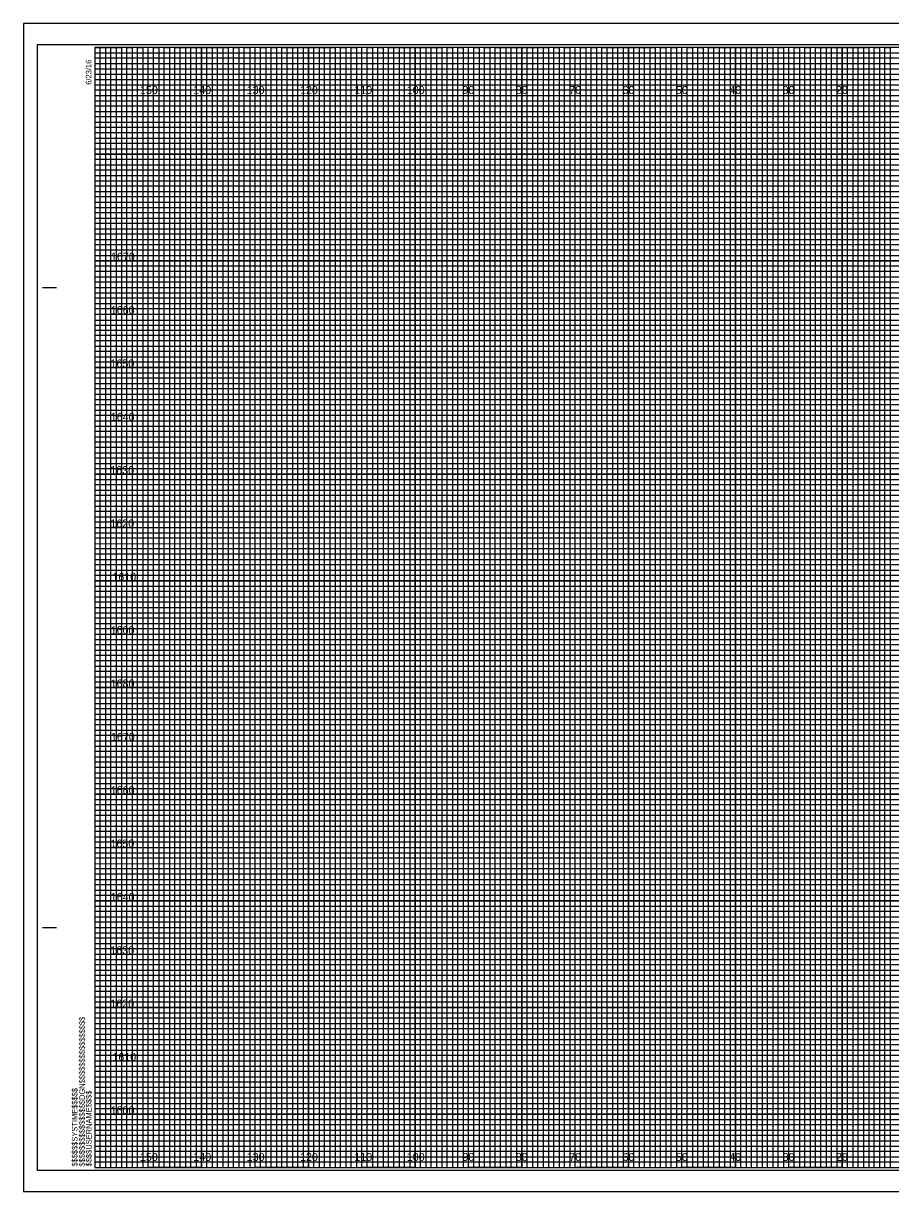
# Model space of a CAD drawing. Extents: x -13 to 323, y -5 to 6154.
# Drawn here: x -13.4 to 149.1, y 5715.5 to 5934.5 of the extents above; entities that cross this region are included whole.
import ezdxf

# ---------------------------------------------------------------- set-up
doc = ezdxf.new("R2010")
doc.units = 0
for name, color, linetype in [('Prop Retaining Wall', 7, 'Continuous'), ('Prop XS Alignment Label', 7, 'Continuous'), ('Prop XS DDE', 7, 'Continuous'), ('Prop XS DDE Elevations', 7, 'Continuous'), ('Prop XS DDE Slope Text', 7, 'Continuous'), ('Prop XS Earthwork Shape', 7, 'Continuous'), ('Prop XS Elevation Labels', 7, 'Continuous'), ('Prop XS Station Labels', 7, 'Continuous'), ('Raster_Level_0', 7, 'Continuous'), ('Scratch_Level_3', 7, 'Continuous'), ('Sheet Cutting Line CELL', 7, 'Continuous')]:
    doc.layers.add(name, color=color, linetype=linetype)

msp = doc.modelspace()

# ---------------------------------------------------------------- linework, layer by layer
at = {"layer": 'Prop Retaining Wall'}
for p, q in [((0, 5929), (260, 5929)), ((260, 5927.98), (0, 5927.98)), ((0, 5927.98), (0, 5927)), ((0, 5927), (260, 5927)), ((260, 5925.89), (0, 5925.89)), ((0, 5925.89), (0, 5924)), ((0, 5924), (320, 5924))]:
    msp.add_line(p, q, dxfattribs=at)
for points in [[(0, 5923), (270, 5923), (320, 5923), (320, 5922), (0, 5922)], [(0, 5921), (320, 5921), (320, 5919), (0, 5919)], [(0, 5918), (320, 5918), (320, 5917), (0, 5916.98)], [(0, 5916), (320, 5916), (320, 5914), (0, 5914)], [(0, 5913), (320, 5913), (320, 5912), (0, 5912)], [(0, 5911), (320, 5911), (320, 5909), (0, 5909)], [(0, 5908), (320, 5908), (320, 5907), (0, 5907)], [(0, 5906), (320, 5906), (320, 5904), (0, 5904)], [(0, 5903), (320, 5903), (320, 5902), (0, 5902)], [(0, 5901), (320, 5901), (320, 5899), (0, 5899)], [(0, 5898), (320, 5898), (320, 5897), (0, 5897)], [(0, 5896), (320, 5896), (320, 5893.95), (320, 5893), (320, 5892), (0, 5892)], [(0, 5894), (320, 5894), (320, 5893), (0, 5893)], [(0, 5891), (320, 5891), (320, 5889), (0, 5889.03)], [(0, 5889.03), (320, 5889), (320, 5888), (0, 5888)], [(0, 5887), (320, 5887), (320, 5886), (0, 5886)], [(0, 5884), (320, 5884), (320, 5883), (0, 5883)], [(0, 5882), (320, 5882), (320, 5881), (0, 5881)], [(-0.07, 5878.89), (320, 5878.89), (320, 5877.88), (-0.07, 5877.88)], [(0, 5877), (320, 5877), (320, 5876), (0, 5876)], [(0, 5874), (320, 5874), (320, 5873), (0, 5873)], [(0, 5872), (320, 5872), (320, 5871), (0, 5871)], [(0, 5869), (320, 5869), (320, 5868), (0, 5868)], [(0, 5867), (320, 5867), (320, 5866), (0, 5866)], [(0, 5864), (320, 5864), (320, 5863), (0, 5863)], [(0, 5862), (320, 5862), (320, 5861), (0, 5861)], [(0, 5859), (320, 5859), (319.99, 5857.98), (0, 5858)], [(0, 5857), (320, 5857), (320, 5856), (0, 5856)], [(0, 5854), (320, 5854), (320, 5853), (0, 5853)], [(0, 5852), (320, 5852), (320, 5851), (0, 5851)], [(0, 5849), (320, 5849), (320, 5848), (0, 5848)], [(0, 5847), (320, 5847), (320, 5846), (0, 5846)], [(0, 5844), (320, 5844), (320, 5843), (0, 5843)], [(0, 5842), (320, 5842), (320, 5841), (0, 5841)], [(0, 5839), (320, 5839), (320, 5838), (0, 5838)], [(0, 5836.99), (320.07, 5836.91), (320, 5836), (0, 5836)], [(0, 5834), (320, 5834), (320, 5833), (0, 5833)], [(0, 5832), (320, 5832), (320, 5831), (0, 5831)], [(0, 5829), (320, 5829), (320, 5828), (0, 5828)], [(0, 5827), (320, 5827), (320, 5826), (0, 5826)], [(0, 5824), (320, 5824), (320, 5823), (0, 5823)], [(0, 5822), (320, 5822), (320, 5821), (0, 5821)], [(0, 5819), (320, 5819), (320, 5818), (0, 5818)], [(0, 5817), (320, 5817), (320, 5816), (0, 5816)], [(0, 5814), (320, 5814), (320, 5813), (0, 5813)], [(0, 5812), (320, 5812), (320, 5811), (0, 5811)], [(0, 5809), (320, 5809), (320, 5808), (0, 5808)], [(0, 5807), (320, 5807), (320, 5806), (0, 5806)], [(0, 5804), (320, 5804), (320, 5803), (0, 5803)], [(0, 5802), (320, 5802), (320, 5801), (0, 5801)], [(0, 5799), (320, 5799), (319.99, 5797.98), (0, 5798)], [(0, 5797), (320, 5797), (320, 5796), (0, 5796)], [(0, 5794), (320, 5794), (320, 5793), (0, 5793)], [(0, 5792), (320, 5792), (320, 5791), (0, 5791)], [(0, 5789), (320, 5789), (320, 5788), (0, 5788)], [(0, 5787), (320, 5787), (320, 5786), (0, 5786)], [(0, 5784), (320, 5784), (320, 5783), (0, 5783)], [(0, 5782), (320, 5782), (320, 5781), (0, 5781)], [(0, 5779), (320, 5779), (320, 5778), (0, 5778)], [(0, 5776.99), (320.07, 5776.91), (320, 5776), (0, 5776)], [(0, 5774), (320, 5774), (320, 5773), (0, 5773)], [(0, 5772), (320, 5772), (320, 5771), (0, 5771)], [(0, 5769), (320, 5769), (320, 5768), (0, 5768)], [(0, 5767), (320, 5767), (320, 5766), (0, 5766)], [(0, 5764), (320, 5764), (320, 5763), (0, 5763)], [(0, 5762), (320, 5762), (320, 5761), (0, 5761)], [(0, 5759), (320, 5759), (320, 5758), (0, 5758)], [(0, 5757), (320, 5757), (320, 5756), (0, 5756)], [(0, 5754), (320, 5754), (320, 5753), (0, 5753)], [(0, 5752), (320, 5752), (320, 5751), (0, 5751)], [(0, 5749), (320, 5749), (320, 5748), (0, 5748)], [(0, 5747), (320, 5747), (320, 5746), (0, 5746)], [(0, 5744), (320, 5744), (320, 5743), (0, 5743)], [(0, 5742), (320, 5742), (320, 5741), (0, 5741)], [(0, 5739), (320, 5739), (320, 5738), (0, 5738)], [(0, 5737), (320, 5737), (320, 5736), (0, 5736)], [(0, 5734), (320, 5734), (320, 5733), (0, 5733)], [(0, 5732), (320, 5732), (320, 5731), (0, 5731)], [(0, 5729), (320, 5729), (320, 5728), (0, 5728)], [(0, 5727), (320, 5727), (320, 5726), (0, 5726)], [(0, 5724), (320, 5724), (320, 5723), (0, 5723)], [(0, 5722), (320, 5722), (320, 5721), (0, 5721)]]:
    msp.add_lwpolyline(points, dxfattribs=at)
at = {"layer": 'Prop XS Alignment Label'}
for p, q in [((-9.8, 5885), (-7.3, 5885)), ((-9.7, 5885), (-7.2, 5885)), ((-9.8, 5765), (-7.3, 5765)), ((-9.7, 5765), (-7.2, 5765)), ((0, 5720), (0, 5720)), ((0, 5720), (0, 5720)), ((0, 5720), (0, 5720)), ((0, 5720), (0, 5720)), ((0, 5720), (0, 5720)), ((0, 5720), (0, 5720)), ((0, 5720), (0, 5720))]:
    msp.add_line(p, q, dxfattribs=at)
msp.add_lwpolyline([(320, 5930), (0, 5930), (0, 5720), (320, 5720)], close=True, dxfattribs=at)
at = {"layer": 'Prop XS DDE'}
msp.add_lwpolyline([(-13.4, 5715.5), (323.3, 5715.5), (323.3, 5934.5), (-13.4, 5934.5)], close=True, dxfattribs=at)
at = {"layer": 'Prop XS DDE Elevations'}
for p, q in [((10, 5720), (10, 5930)), ((20, 5720), (20, 5930)), ((30, 5720), (30, 5930)), ((40, 5720), (40, 5930)), ((50, 5720), (50, 5930)), ((60, 5720), (60, 5930)), ((70, 5720), (70, 5930)), ((80, 5720), (80, 5930)), ((90, 5720), (90, 5930)), ((100, 5720), (100, 5930)), ((110, 5720), (110, 5930)), ((120, 5720), (120, 5930)), ((130, 5720), (130, 5930)), ((140, 5720), (140, 5930)), ((0, 5920), (320, 5920)), ((0, 5910), (320, 5910)), ((0, 5900), (320, 5900)), ((0, 5890), (320, 5890)), ((0, 5880), (320, 5880)), ((0, 5870), (320, 5870)), ((0, 5860), (320, 5860)), ((0, 5850), (320, 5850)), ((0, 5840), (320, 5840)), ((0, 5830), (320, 5830)), ((0, 5820), (320, 5820)), ((0, 5810), (320, 5810)), ((0, 5800), (320, 5800)), ((0, 5790), (320, 5790)), ((0, 5780), (320, 5780)), ((0, 5770), (320, 5770)), ((0, 5760), (320, 5760)), ((0, 5750), (320, 5750)), ((0, 5740), (320, 5740)), ((0, 5730), (320, 5730))]:
    msp.add_line(p, q, dxfattribs=at)
at = {"layer": 'Prop XS DDE Slope Text'}
msp.add_lwpolyline([(-10.8, 5719.5), (322.4, 5719.5), (322.4, 5930.5), (-10.8, 5930.5)], close=True, dxfattribs=at)
at = {"layer": 'Prop XS Earthwork Shape'}
for p, q in [((10, 5930), (0, 5930)), ((10, 5720), (10, 5930)), ((30, 5930), (20, 5930)), ((20, 5930), (20, 5720)), ((30, 5720), (30, 5930)), ((50, 5930), (40, 5930)), ((40, 5930), (40, 5720)), ((50, 5720), (50, 5930)), ((70, 5930), (60, 5930)), ((60, 5930), (60, 5720)), ((70, 5720), (70, 5930)), ((90, 5930), (80, 5930)), ((80, 5930), (80, 5720)), ((90, 5720), (90, 5930)), ((110, 5930), (100, 5930)), ((100, 5930), (100, 5720)), ((110, 5720), (110, 5930)), ((130, 5930), (120, 5930)), ((120, 5930), (120, 5720)), ((130, 5720), (130, 5930)), ((150, 5930), (140, 5930)), ((140, 5930), (140, 5720)), ((20, 5720), (10, 5720)), ((40, 5720), (30, 5720)), ((60, 5720), (50, 5720)), ((80, 5720), (70, 5720)), ((100, 5720), (90, 5720)), ((120, 5720), (110, 5720)), ((140, 5720), (130, 5720))]:
    msp.add_line(p, q, dxfattribs=at)
for points in [[(0, 5920), (320, 5920), (320, 5910), (0, 5910)], [(0, 5900), (320, 5900), (320, 5890), (0, 5890)], [(0, 5880), (320, 5880), (320, 5870), (0, 5870)], [(0, 5860), (320, 5860), (320, 5850), (0, 5850)], [(0, 5840), (320, 5840), (320, 5830), (0, 5830)], [(0, 5820), (320, 5820), (320, 5810), (0, 5810)], [(0, 5800), (320, 5800), (320, 5790), (0, 5790)], [(0, 5780), (320, 5780), (320, 5770), (0, 5770)], [(0, 5760), (320, 5760), (320, 5750), (0, 5750)], [(0, 5740), (320, 5740), (320, 5730), (0, 5730)]]:
    msp.add_lwpolyline(points, dxfattribs=at)
at = {"layer": 'Prop XS Elevation Labels'}
for points in [[(0, 5720), (1, 5720), (1, 5930), (2, 5930), (2, 5720)], [(2, 5720), (3, 5720), (3, 5930), (4, 5930), (4, 5720)], [(5, 5720), (6, 5720), (6, 5930), (7, 5930), (7, 5720)], [(7, 5720), (8, 5720), (8, 5930), (9, 5930), (9, 5720)], [(10, 5720), (11, 5720), (11, 5930), (12, 5930), (12, 5720)], [(12, 5720), (13, 5720), (13, 5930), (14, 5930), (14, 5720)], [(15, 5720), (16, 5720), (16, 5930), (17, 5930), (17, 5720)], [(17, 5720), (18, 5720), (18, 5930), (19, 5930), (19, 5720)], [(20, 5720), (21, 5720), (21, 5930), (22, 5930), (22, 5720)], [(22, 5720), (23, 5720), (23, 5930), (24, 5930), (24, 5720)], [(25, 5720), (26, 5720), (26, 5930), (27, 5930), (27, 5720)], [(27, 5720), (28, 5720), (28, 5930), (29, 5930), (29, 5720)], [(30, 5720), (31, 5720), (31, 5930), (32, 5930), (32, 5720)], [(32, 5720), (33, 5720), (33, 5930), (34, 5930), (34, 5720)], [(35, 5720), (36, 5720), (36, 5930), (37, 5930), (37, 5720)], [(37, 5720), (38, 5720), (38, 5930), (39, 5930), (39, 5720)], [(40, 5720), (41, 5720), (41, 5930), (42, 5930), (42, 5720)], [(42, 5720), (43, 5720), (43, 5930), (44, 5930), (44, 5720)], [(45, 5720), (46, 5720), (46, 5930), (47, 5930), (47, 5720)], [(47, 5720), (48, 5720), (48, 5930), (49, 5930), (49, 5720)], [(50, 5720), (51, 5720), (51, 5930), (52, 5930), (52, 5720)], [(52, 5720), (53, 5720), (53, 5930), (54, 5930), (54, 5720)], [(55, 5720), (56, 5720), (56, 5930), (57, 5930), (57, 5720)], [(57, 5720), (58, 5720), (58, 5930), (59, 5930), (59, 5720)], [(60, 5720), (61, 5720), (61, 5930), (62, 5930), (62, 5720)], [(62, 5720), (63, 5720), (63, 5930), (64, 5930), (64, 5720)], [(65, 5720), (66, 5720), (66, 5930), (67, 5930), (67, 5720)], [(67, 5720), (68, 5720), (68, 5930), (69, 5930), (69, 5720)], [(70, 5720), (71, 5720), (71, 5930), (72, 5930), (72, 5720)], [(72, 5720), (73, 5720), (73, 5930), (74, 5930), (74, 5720)], [(75, 5720), (76, 5720), (76, 5930), (77, 5930), (77, 5720)], [(77, 5720), (78, 5720), (78, 5930), (79, 5930), (79, 5720)], [(80, 5720), (81, 5720), (81, 5930), (82, 5930), (82, 5720)], [(82, 5720), (83, 5720), (83, 5930), (84, 5930), (84, 5720)], [(85, 5720), (86, 5720), (86, 5930), (87, 5930), (87, 5720)], [(87, 5720), (88, 5720), (88, 5930), (89, 5930), (89, 5720)], [(90, 5720), (91, 5720), (91, 5930), (92, 5930), (92, 5720)], [(92, 5720), (93, 5720), (93, 5930), (94, 5930), (94, 5720)], [(95, 5720), (96, 5720), (96, 5930), (97, 5930), (97, 5720)], [(97, 5720), (98, 5720), (98, 5930), (99, 5930), (99, 5720)], [(100, 5720), (101, 5720), (101, 5930), (102, 5930), (102, 5720)], [(102, 5720), (103, 5720), (103, 5930), (104, 5930), (104, 5720)], [(105, 5720), (106, 5720), (106, 5930), (107, 5930), (107, 5720)], [(107, 5720), (108, 5720), (108, 5930), (109, 5930), (109, 5720)], [(110, 5720), (111, 5720), (111, 5930), (112, 5930), (112, 5720)], [(112, 5720), (113, 5720), (113, 5930), (114, 5930), (114, 5720)], [(115, 5720), (116, 5720), (116, 5930), (117, 5930), (117, 5720)], [(117, 5720), (118, 5720), (118, 5930), (119, 5930), (119, 5720)], [(120, 5720), (121, 5720), (121, 5930), (122, 5930), (122, 5720)], [(122, 5720), (123, 5720), (123, 5930), (124, 5930), (124, 5720)], [(125, 5720), (126, 5720), (126, 5930), (127, 5930), (127, 5720)], [(127, 5720), (128, 5720), (128, 5930), (129, 5930), (129, 5720)], [(130, 5720), (131, 5720), (131, 5930), (132, 5930), (132, 5720)], [(132, 5720), (133, 5720), (133, 5930), (134, 5930), (134, 5720)], [(135, 5720), (136, 5720), (136, 5930), (137, 5930), (137, 5720)], [(137, 5720), (138, 5720), (138, 5930), (139, 5930), (139, 5720)], [(140, 5720), (141, 5720), (141, 5930), (142, 5930), (142, 5720)], [(142, 5720), (143, 5720), (143, 5930), (144, 5930), (144, 5720)], [(145, 5720), (146, 5720), (146, 5930), (147, 5930), (147, 5720)], [(147, 5720), (148, 5720), (148, 5930), (149, 5930), (149, 5720)]]:
    msp.add_lwpolyline(points, dxfattribs=at)
at = {"layer": 'Prop XS Station Labels'}
for points in [[(0, 5930), (5, 5930), (5, 5720), (15, 5720), (15, 5930), (25, 5930), (25, 5720), (35, 5720), (35, 5930), (45, 5930), (45, 5720), (55, 5720), (55, 5930), (65, 5930), (65, 5720), (75, 5720), (75, 5930), (85, 5930), (85, 5720), (95, 5720), (95, 5930), (105, 5930), (105, 5720), (115, 5720), (115, 5930), (125, 5930), (125, 5720), (135, 5720), (135, 5930), (145, 5930), (145, 5720), (155, 5720)], [(0, 5925), (275, 5925)], [(0, 5905), (320, 5905), (320, 5915), (0, 5915)], [(0, 5885), (320, 5885), (320, 5895), (0, 5895)], [(0, 5865), (320, 5865), (320, 5875), (0, 5875)], [(0, 5845), (320, 5845), (320, 5855), (0, 5855)], [(0, 5825), (320, 5825), (320, 5835), (0, 5835)], [(0, 5805), (320, 5805), (320, 5815), (0, 5815)], [(0, 5785), (320, 5785), (320, 5795), (0, 5795)], [(0, 5765), (320, 5765), (320, 5775), (0, 5775)], [(0, 5745), (320, 5745), (320, 5755), (0, 5755)], [(0, 5725), (320, 5725), (320, 5735), (0, 5735)]]:
    msp.add_lwpolyline(points, dxfattribs=at)
at = {"layer": 'Sheet Cutting Line CELL'}
for p, q in [((323.3, 5934.5), (-13.4, 5934.5)), ((-13.4, 5934.5), (-13.4, 5715.5)), ((-13.4, 5715.5), (323.3, 5715.5))]:
    msp.add_line(p, q, dxfattribs=at)

# ---------------------------------------------------------------- texts
at = {"layer": 'Prop XS Alignment Label'}
for s, p in [('6/23/16', (-0.65, 5923)), ('$$$$$$$$$$$$$$$$DGN$$$$$$$$$$$$$$$$', (-1.88, 5720.18)), ('$$$$$$SYSTIME$$$$$', (-3.26, 5720.18)), ('$$$$USERNAME$$$$', (-0.62, 5720.23))]:
    msp.add_text(s, height=1.05, rotation=90, dxfattribs=at).set_placement(p)
at = {"layer": 'Raster_Level_0'}
for s, p in [('150', (8.44, 5921.25)), ('140', (18.44, 5921.25)), ('130', (28.44, 5921.25)), ('120', (38.44, 5921.25)), ('110', (48.62, 5921.25)), ('100', (58.44, 5921.25)), ('90', (68.86, 5921.25)), ('80', (78.86, 5921.25)), ('70', (88.86, 5921.25)), ('60', (98.86, 5921.25)), ('50', (108.86, 5921.25)), ('40', (118.86, 5921.25)), ('30', (128.86, 5921.25)), ('20', (138.86, 5921.25)), ('150', (8.44, 5721.25)), ('140', (18.44, 5721.25)), ('130', (28.44, 5721.25)), ('120', (38.44, 5721.25)), ('110', (48.62, 5721.25)), ('100', (58.44, 5721.25)), ('90', (68.86, 5721.25)), ('80', (78.86, 5721.25)), ('70', (88.86, 5721.25)), ('60', (98.86, 5721.25)), ('50', (108.86, 5721.25)), ('40', (118.86, 5721.25)), ('30', (128.86, 5721.25)), ('20', (138.86, 5721.25))]:
    msp.add_text(s, height=1.5, dxfattribs=at).set_placement(p)
at = {"layer": 'Scratch_Level_3'}
for s, p in [('1670', (3, 5890)), ('1660', (2.97, 5880)), ('1650', (2.92, 5870)), ('1640', (2.97, 5860)), ('1630', (2.89, 5850)), ('1620', (2.9, 5840)), ('1610', (3.28, 5830)), ('1600', (2.95, 5820)), ('1680', (2.95, 5810)), ('1670', (3, 5800)), ('1660', (2.97, 5790)), ('1650', (2.92, 5780)), ('1640', (2.97, 5770)), ('1630', (2.89, 5760)), ('1620', (2.9, 5750)), ('1610', (3.28, 5740)), ('1600', (2.95, 5730))]:
    msp.add_text(s, height=1.5, dxfattribs=at).set_placement(p)

doc.saveas('drawing.dxf')
